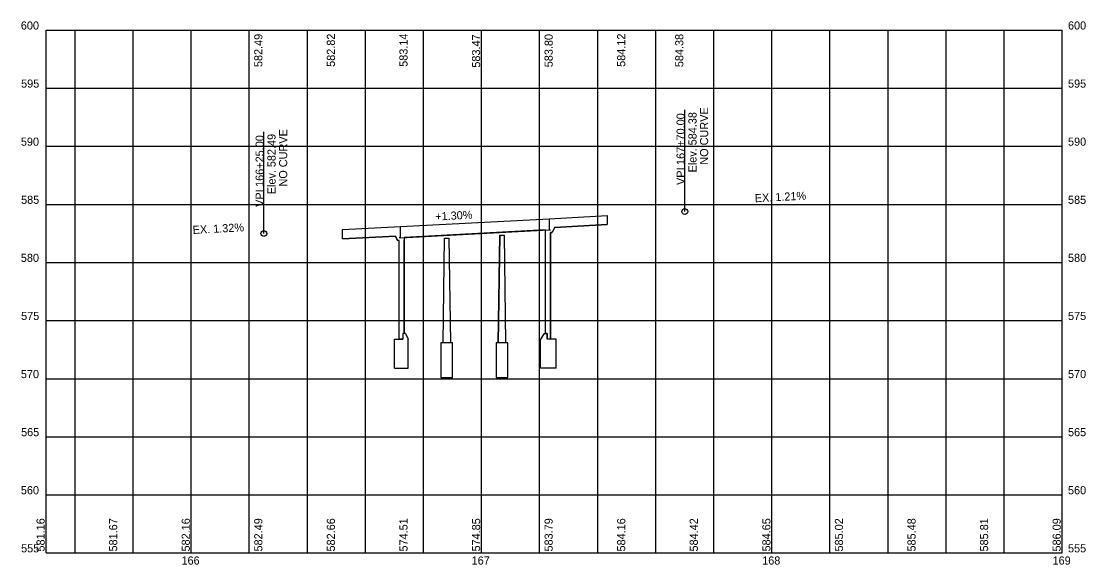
# Model space of a CAD drawing. Extents: x 91 to 458, y 551 to 738.
import ezdxf

# ---------------------------------------------------------------- set-up
doc = ezdxf.new("R2010")
doc.units = 0
for name, color, linetype in [('PF_X_Ground_Line', 7, 'Continuous'), ('PV_P_EOP', 7, 'Continuous'), ('RW_P_Esmt_SH', 7, 'Continuous'), ('RW_P_Esmt_TMP', 7, 'Continuous'), ('RW_X_CL_100_Distances', 7, 'Continuous'), ('RW_X_Esmt_U', 7, 'Continuous'), ('SC_Scratch1', 7, 'Continuous'), ('SV_X_Control_Cells_Found', 7, 'Continuous'), ('UT_X_Gas', 7, 'Continuous'), ('UT_X_Water', 7, 'Continuous')]:
    doc.layers.add(name, color=color, linetype=linetype)

msp = doc.modelspace()

# ---------------------------------------------------------------- linework, layer by layer
at = {"layer": 'PF_X_Ground_Line'}
for p, q in [((220, 618.6), (220, 628.6)), ((220, 628.6), (222.84, 628.6)), ((223.84, 630.6), (222.84, 630.6)), ((222.84, 630.6), (222.84, 628.6)), ((223.84, 630.6), (224.67, 628.6)), ((224.67, 618.6), (224.67, 628.6)), ((240, 627.4), (236, 627.4)), ((236, 627.4), (236, 615.4)), ((240, 615.4), (240, 627.4)), ((259, 627.4), (255, 627.4)), ((255, 627.4), (255, 615.4)), ((259, 615.4), (259, 627.4)), ((271.54, 630.6), (270.33, 628.6)), ((270.33, 618.6), (270.33, 628.6)), ((271.54, 630.6), (272.54, 630.6)), ((272.54, 630.6), (272.54, 628.6)), ((275.75, 628.6), (272.54, 628.6)), ((275.75, 618.6), (275.75, 628.6)), ((220, 618.6), (224.67, 618.6)), ((275.75, 618.6), (270.33, 618.6)), ((236, 615.4), (240, 615.4)), ((255, 615.4), (259, 615.4))]:
    msp.add_line(p, q, dxfattribs=at)
at = {"layer": 'PV_P_EOP'}
for points in [[(202.09, 666.39), (222.09, 667.43), (273.29, 670.09), (293.29, 671.13), (293.29, 668.04), (275.18, 667.06), (274.29, 665.28), (273.79, 665.28), (273.79, 628.6), (272.54, 628.6), (272.54, 630.6), (272.04, 630.6), (272.04, 666.21), (223.34, 663.59), (223.34, 630.6), (222.84, 630.6), (222.84, 628.6), (221.59, 628.6), (221.59, 662.52), (221.09, 662.52), (220.3, 664.1), (202.09, 663.12)], [(255.75, 627.4), (256.25, 664.36), (257.75, 664.44), (258.25, 627.4)], [(236.75, 627.4), (237.25, 663.34), (238.75, 663.42), (239.25, 627.4)]]:
    msp.add_lwpolyline(points, close=True, dxfattribs=at)
at = {"layer": 'RW_P_Esmt_SH'}
msp.add_line((222.09, 663.52), (273.29, 666.28), dxfattribs=at)
at = {"layer": 'RW_P_Esmt_TMP'}
for p, q in [((222.09, 663.52), (222.09, 667.43)), ((273.29, 670.09), (273.29, 666.28)), ((256.25, 664.36), (255.75, 627.4)), ((257.75, 664.44), (258.25, 627.4)), ((272.04, 630.6), (272.04, 665.21)), ((273.29, 666.28), (273.79, 666.28)), ((273.79, 628.6), (273.79, 665.28)), ((222.09, 663.52), (221.59, 663.52)), ((221.59, 628.6), (221.59, 662.52)), ((223.34, 630.6), (223.34, 662.59)), ((236.75, 627.4), (237.25, 663.34)), ((238.75, 663.42), (239.25, 627.4))]:
    msp.add_line(p, q, dxfattribs=at)
at = {"layer": 'RW_X_CL_100_Distances'}
for p, q in [((100, 735), (450, 735)), ((100, 555), (100, 735)), ((110, 555), (110, 735)), ((130, 555), (130, 735)), ((150, 555), (150, 735)), ((170, 555), (170, 735)), ((190, 555), (190, 735)), ((210, 555), (210, 735)), ((230, 555), (230, 735)), ((250, 555), (250, 735)), ((270, 555), (270, 735)), ((290, 555), (290, 735)), ((310, 555), (310, 735)), ((330, 555), (330, 735)), ((350, 555), (350, 735)), ((370, 555), (370, 735)), ((390, 555), (390, 735)), ((410, 555), (410, 735)), ((430, 555), (430, 735)), ((450, 555), (450, 735)), ((100, 715), (450, 715)), ((100, 695), (450, 695)), ((100, 675), (450, 675)), ((100, 655), (450, 655)), ((100, 635), (450, 635)), ((100, 615), (450, 615)), ((100, 595), (450, 595)), ((100, 575), (450, 575)), ((100, 555), (450, 555))]:
    msp.add_line(p, q, dxfattribs=at)
at = {"layer": 'RW_X_Esmt_U'}
for p, q in [((293.29, 671.13), (293.29, 668.04)), ((275.18, 667.06), (293.29, 668.04)), ((202.09, 663.12), (202.09, 666.39)), ((202.09, 663.12), (220.3, 664.1)), ((220.3, 664.1), (221.09, 662.52)), ((273.79, 665.28), (274.29, 665.28)), ((275.18, 667.06), (274.29, 665.28)), ((221.59, 662.52), (221.09, 662.52))]:
    msp.add_line(p, q, dxfattribs=at)
at = {"layer": 'SC_Scratch1'}
for p, q in [((320, 672.53), (320, 707.53)), ((175, 664.98), (175, 699.98))]:
    msp.add_line(p, q, dxfattribs=at)
for centre in [(320, 672.53), (175, 664.98)]:
    msp.add_circle(centre, 1, dxfattribs=at)
at = {"layer": 'SV_X_Control_Cells_Found'}
for p, q in [((320, 672.53), (320, 707.53)), ((175, 664.98), (175, 699.98))]:
    msp.add_line(p, q, dxfattribs=at)
for centre in [(320, 672.53), (175, 664.98)]:
    msp.add_circle(centre, 1, dxfattribs=at)

# ---------------------------------------------------------------- texts
at = {"layer": 'PF_X_Ground_Line'}
for s, p in [('600', (91.31, 735.2)), ('600', (452, 735.2)), ('595', (91.39, 715.2)), ('595', (452, 715.2)), ('590', (91.31, 695.2)), ('590', (452, 695.2)), ('585', (91.39, 675.2)), ('585', (452, 675.2)), ('580', (91.31, 655.2)), ('580', (452, 655.2)), ('575', (91.39, 635.2)), ('575', (452, 635.2)), ('570', (91.31, 615.2)), ('570', (452, 615.2)), ('565', (91.39, 595.2)), ('565', (452, 595.2)), ('560', (91.31, 575.2)), ('560', (452, 575.2)), ('555', (91.39, 555.2)), ('555', (452, 555.2)), ('166', (146.64, 551)), ('167', (246.58, 551)), ('168', (346.66, 551)), ('169', (446.68, 551))]:
    msp.add_text(s, height=2.8, dxfattribs=at).set_placement(p)
at = {"layer": 'SC_Scratch1'}
for s, rotation, p in [('NO CURVE', 90, (328.05, 688.67)), ('167+70.00', 90, (319.96, 688.58)), ('584.38', 90, (324.05, 695.34)), ('NO CURVE', 90, (183.05, 681.15)), ('166+25.00', 90, (174.96, 681.03)), ('582.49', 90, (179.05, 687.82)), ('Elev. ', 90, (324.05, 686.02)), ('Elev. ', 90, (179.05, 678.5)), ('VPI ', 90, (319.96, 681.69)), ('VPI ', 90, (174.96, 674.14)), ('EX. 1.21%', 3.008, (344.18, 675.73)), ('+1.30%', 2.9808, (234.12, 669.43)), ('EX. 1.32%', 3.008, (150.56, 664.82))]:
    msp.add_text(s, height=2.8, rotation=rotation, dxfattribs=at).set_placement(p)
at = {"layer": 'SV_X_Control_Cells_Found'}
for s, p in [('167+70.00', (319.96, 688.58)), ('584.38', (324.05, 695.34)), ('166+25.00', (174.96, 681.03)), ('582.49', (179.05, 687.82)), ('Elev. ', (324.05, 686.02)), ('Elev. ', (179.05, 678.5)), ('VPI ', (319.96, 681.69)), ('VPI ', (174.96, 674.14))]:
    msp.add_text(s, height=2.8, rotation=90, dxfattribs=at).set_placement(p)
at = {"layer": 'UT_X_Gas'}
for s, p in [('582.49', (174.5, 722.28)), ('582.49', (174.5, 722.28)), ('582.82', (199.5, 722.36)), ('582.82', (199.5, 722.36)), ('583.14', (224.5, 722.37)), ('583.14', (224.5, 722.37)), ('583.47', (249.5, 722.08)), ('583.47', (249.5, 722.08)), ('583.80', (274.5, 722.22)), ('583.80', (274.5, 722.22)), ('584.12', (299.5, 722.36)), ('584.12', (299.5, 722.36)), ('584.38', (319.5, 722.25)), ('584.38', (319.5, 722.25))]:
    msp.add_text(s, height=2.8, rotation=90, dxfattribs=at).set_placement(p)
at = {"layer": 'UT_X_Water'}
for s, p in [('581.16', (99.5, 555.5)), ('581.67', (124.5, 555.5)), ('582.16', (149.5, 555.5)), ('582.49', (174.5, 555.5)), ('582.66', (199.5, 555.5)), ('574.51', (224.5, 555.5)), ('574.85', (249.51, 555.5)), ('583.79', (274.5, 555.5)), ('584.16', (299.5, 555.5)), ('584.42', (324.5, 555.5)), ('584.65', (349.5, 555.5)), ('585.02', (374.5, 555.5)), ('585.48', (399.5, 555.5)), ('585.81', (424.5, 555.5)), ('586.09', (449.5, 555.5))]:
    msp.add_text(s, height=2.8, rotation=90, dxfattribs=at).set_placement(p)

doc.saveas('drawing.dxf')
